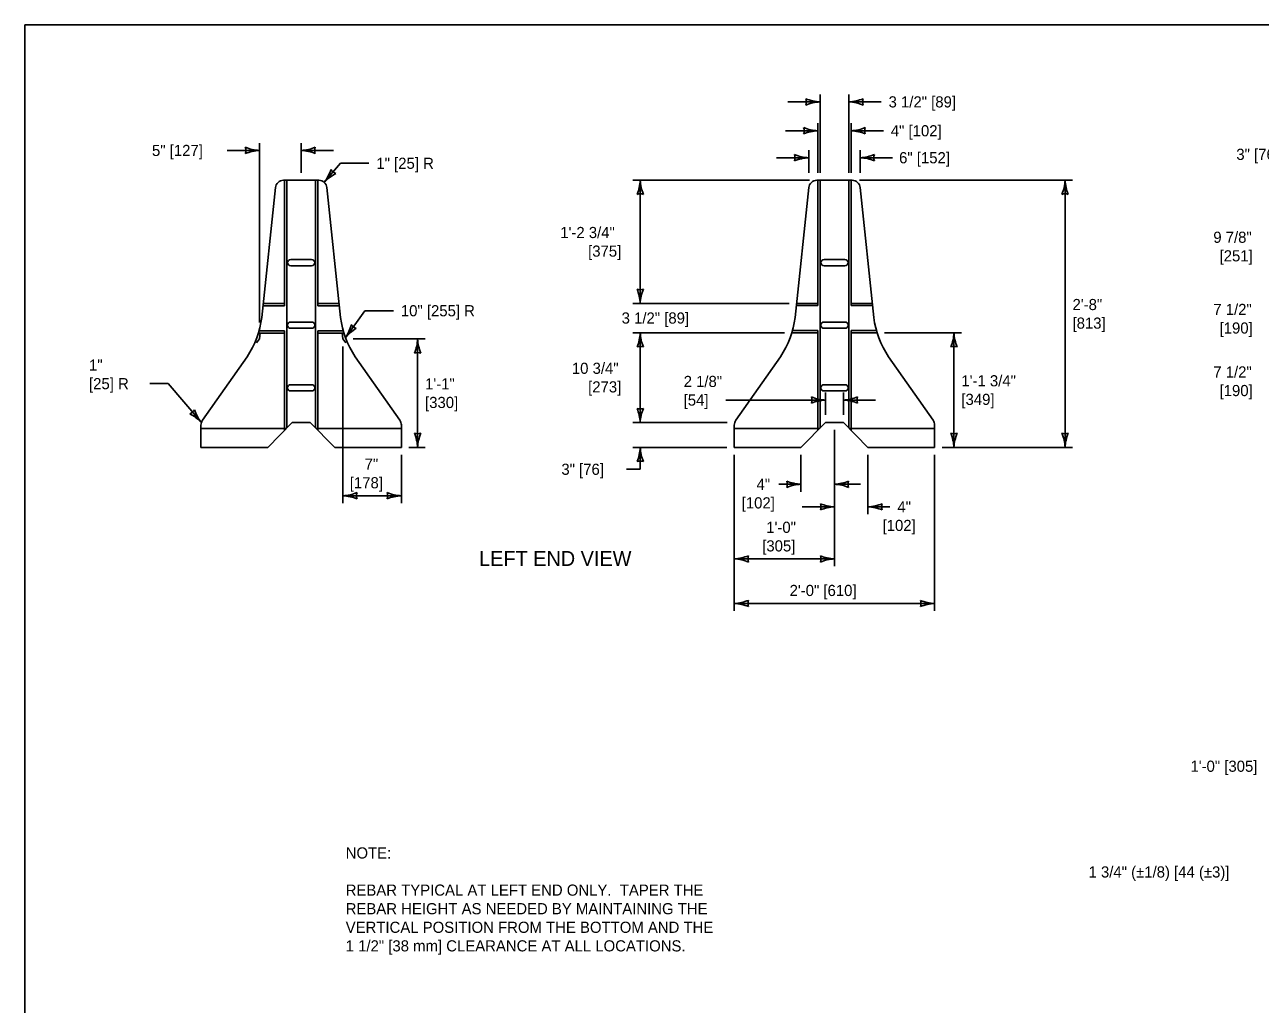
# Model space of a CAD drawing. Extents: x 49991.4 to 50021, y 49987.6 to 50011.4.
# Drawn here: x 49999.38 to 50006.04, y 49993.73 to 49999 of the extents above; entities that cross this region are included whole.
import ezdxf

# ---------------------------------------------------------------- set-up
doc = ezdxf.new("R2010")
doc.units = 0
for name, color, linetype in [('Level 1', 7, 'Continuous'), ('Level 2', 7, 'Continuous'), ('Level 3', 7, 'Continuous'), ('Level 4', 7, 'Continuous')]:
    doc.layers.add(name, color=color, linetype=linetype)

msp = doc.modelspace()

# ---------------------------------------------------------------- linework, layer by layer
at = {"layer": 'Level 1'}
for p, q in [((50000.9678, 49998.1625), (50000.776, 49998.1625)), ((50000.7821, 49998.1625), (50000.7821, 49997.4862)), ((50000.7945, 49998.1625), (50000.7944, 49996.8293)), ((50000.9495, 49998.1625), (50000.9494, 49996.8294)), ((50000.9618, 49998.1625), (50000.9618, 49997.4862)), ((50003.8378, 49998.1624), (50003.6484, 49998.1624)), ((50003.6533, 49998.1624), (50003.6533, 49997.4888)), ((50003.6653, 49998.1624), (50003.6653, 49996.8289)), ((50003.821, 49998.1624), (50003.821, 49996.8288)), ((50003.8329, 49998.1624), (50003.8329, 49997.4888)), ((50000.6596, 49997.4243), (50000.7333, 49998.123)), ((50001.0843, 49997.4242), (50001.0105, 49998.123)), ((50003.5308, 49997.4242), (50003.6046, 49998.1228)), ((50003.9555, 49997.4242), (50003.8817, 49998.1228)), ((50000.8158, 49997.7355), (50000.9281, 49997.7355)), ((50000.8158, 49997.7018), (50000.9281, 49997.7018)), ((50003.6869, 49997.7354), (50003.7993, 49997.7354)), ((50003.6869, 49997.7017), (50003.7993, 49997.7017)), ((50000.7821, 49997.4862), (50000.6661, 49997.4862)), ((50000.7821, 49997.4982), (50000.6674, 49997.4982)), ((50001.0765, 49997.4982), (50000.9618, 49997.4982)), ((50000.9618, 49997.4862), (50001.0777, 49997.4862)), ((50003.6533, 49997.4888), (50003.5376, 49997.4888)), ((50003.6533, 49997.4999), (50003.5388, 49997.4999)), ((50003.9475, 49997.4999), (50003.8329, 49997.4999)), ((50003.8329, 49997.4888), (50003.9487, 49997.4888)), ((50000.6459, 49997.3519), (50000.7821, 49997.3519)), ((50000.7821, 49997.3519), (50000.7821, 49996.8167)), ((50000.9281, 49997.3995), (50000.8158, 49997.3995)), ((50000.8158, 49997.3658), (50000.9281, 49997.3658)), ((50001.098, 49997.3519), (50000.9618, 49997.3519)), ((50000.9618, 49997.3519), (50000.9618, 49996.8168)), ((50003.5178, 49997.3543), (50003.6533, 49997.3543)), ((50003.6533, 49997.3543), (50003.6533, 49996.8167)), ((50003.7993, 49997.3994), (50003.6869, 49997.3994)), ((50003.6869, 49997.3657), (50003.7993, 49997.3657)), ((50003.8329, 49997.3543), (50003.8329, 49996.8167)), ((50003.9685, 49997.3543), (50003.8329, 49997.3543)), ((50000.7821, 49997.3399), (50000.6424, 49997.3399)), ((50001.1014, 49997.3399), (50000.9618, 49997.3399)), ((50003.6533, 49997.3417), (50003.5142, 49997.3417)), ((50003.9721, 49997.3417), (50003.8329, 49997.3417)), ((50000.3405, 49996.8706), (50000.5804, 49997.2129)), ((50001.4033, 49996.8706), (50001.1634, 49997.2129)), ((50003.2118, 49996.8705), (50003.4517, 49997.2128)), ((50004.2745, 49996.8705), (50004.0347, 49997.2128)), ((50000.9281, 49997.0621), (50000.8158, 49997.0621)), ((50000.8158, 49997.0284), (50000.9281, 49997.0284)), ((50003.7993, 49997.062), (50003.6869, 49997.062)), ((50003.6869, 49997.0283), (50003.7993, 49997.0283)), ((50000.3326, 49996.7248), (50000.3325, 49996.8452)), ((50000.6916, 49996.7248), (50000.8239, 49996.8592)), ((50000.9201, 49996.8592), (50000.8239, 49996.8592)), ((50001.0523, 49996.7248), (50000.9201, 49996.8592)), ((50001.4114, 49996.7248), (50001.4113, 49996.8453)), ((50003.2037, 49996.7247), (50003.2038, 49996.8451)), ((50003.5627, 49996.7247), (50003.695, 49996.8591)), ((50003.695, 49996.8591), (50003.7912, 49996.8591)), ((50003.9235, 49996.7247), (50003.7912, 49996.8591)), ((50004.2825, 49996.7247), (50004.2825, 49996.8451)), ((50000.3326, 49996.7248), (50000.6916, 49996.7248)), ((50001.4114, 49996.7248), (50001.0523, 49996.7248)), ((50003.2037, 49996.7247), (50003.5627, 49996.7247)), ((50004.2825, 49996.7247), (50003.9235, 49996.7247))]:
    msp.add_line(p, q, dxfattribs=at)
msp.add_lwpolyline([(49999.3835, 49998.9992), (50016.7501, 49998.9992), (50016.7501, 49987.7988), (49999.3835, 49987.7988)], close=True, dxfattribs=at)
for centre, radius, start, end in [((50000.7773, 49998.1183), 0.0442, 91.675, 173.90567), ((50000.9665, 49998.1183), 0.0442, 6.02753, 88.325), ((50003.6485, 49998.1182), 0.0442, 90.18102, 173.97247), ((50003.8378, 49998.1182), 0.0442, 6.02753, 89.95602), ((50000.8158, 49997.7186), 0.0168, 90, 270), ((50000.9281, 49997.7186), 0.0168, 270, 89.99999), ((50003.6869, 49997.7185), 0.0168, 90, 270), ((50003.7993, 49997.7185), 0.0168, 270, 89.99999), ((50000.2111, 49997.4717), 0.4509, 324.97771, 353.97247), ((50001.5327, 49997.4717), 0.4509, 186.04429, 215.02228), ((50003.0824, 49997.4716), 0.451, 324.97771, 353.97053), ((50004.404, 49997.4716), 0.451, 186.02753, 215.02228), ((50000.8158, 49997.3826), 0.0168, 90, 270), ((50000.9281, 49997.3826), 0.0168, 270, 89.99999), ((50003.6869, 49997.3825), 0.0168, 90, 270), ((50003.7993, 49997.3825), 0.0168, 270, 89.99999), ((50000.8158, 49997.0453), 0.0168, 90, 270), ((50000.9281, 49997.0453), 0.0168, 270, 89.99999), ((50003.6869, 49997.0451), 0.0168, 90, 270), ((50003.7993, 49997.0451), 0.0168, 270, 90), ((50000.3767, 49996.8452), 0.0442, 144.97771, 180), ((50001.3671, 49996.8453), 0.0442, 0, 35.02229), ((50003.248, 49996.8451), 0.0442, 144.97771, 180), ((50004.2383, 49996.8451), 0.0442, 0, 35.02229)]:
    msp.add_arc(centre, radius, start, end, dxfattribs=at)
at = {"layer": 'Level 3'}
for p, q in [((50003.6653, 49998.2024), (50003.6653, 49998.624)), ((50003.821, 49998.2024), (50003.821, 49998.624)), ((50003.6653, 49998.584), (50003.4919, 49998.584)), ((50003.821, 49998.584), (50003.9944, 49998.584)), ((50003.6533, 49998.4286), (50003.4799, 49998.4286)), ((50003.6533, 49998.2024), (50003.6533, 49998.4686)), ((50003.8329, 49998.2024), (50003.8329, 49998.4686)), ((50003.8329, 49998.4286), (50004.0063, 49998.4286)), ((50000.6473, 49997.3971), (50000.6473, 49998.3627)), ((50000.872, 49998.2025), (50000.872, 49998.3627)), ((50000.6473, 49998.3227), (50000.4738, 49998.3227)), ((50001.0454, 49998.3227), (50000.872, 49998.3227)), ((50003.6046, 49998.2835), (50003.4311, 49998.2835)), ((50003.6046, 49998.2024), (50003.6046, 49998.3235)), ((50003.8817, 49998.2024), (50003.8817, 49998.3235)), ((50003.8817, 49998.2835), (50004.0552, 49998.2835)), ((50000.9961, 49998.1512), (50001.083, 49998.2535)), ((50001.083, 49998.2535), (50001.2368, 49998.2535)), ((50003.6084, 49998.1624), (50002.6573, 49998.1624)), ((50002.6973, 49997.4999), (50002.6973, 49998.1624)), ((50003.8778, 49998.1624), (50005.0247, 49998.1624)), ((50004.9847, 49998.1624), (50004.9847, 49996.7247)), ((50003.4988, 49997.4999), (50002.6573, 49997.4999)), ((50001.1104, 49997.3135), (50001.2154, 49997.4602)), ((50001.2154, 49997.4602), (50001.3687, 49997.4602)), ((50000.6473, 49997.3084), (50000.632, 49997.2865)), ((50000.6508, 49997.3413), (50000.6473, 49997.3084)), ((50001.0931, 49997.3413), (50001.0965, 49997.3084)), ((50001.0965, 49997.3084), (50001.1119, 49997.2865)), ((50001.1524, 49997.3084), (50001.539, 49997.3084)), ((50001.499, 49996.7248), (50001.499, 49997.3084)), ((50003.4742, 49997.3417), (50002.6573, 49997.3417)), ((50002.6973, 49997.3417), (50002.6973, 49996.8584)), ((50004.0121, 49997.3417), (50004.4264, 49997.3417)), ((50004.3864, 49996.7247), (50004.3864, 49997.3417)), ((50001.0965, 49997.2684), (50001.0965, 49996.4245)), ((50000.1561, 49997.0678), (50000.0563, 49997.0678)), ((50000.3346, 49996.8585), (50000.1561, 49997.0678)), ((50003.695, 49996.8991), (50003.695, 49997.0196)), ((50003.7912, 49996.8991), (50003.7912, 49997.0196)), ((50003.695, 49996.9796), (50003.1577, 49996.9796)), ((50003.7912, 49996.9796), (50003.9646, 49996.9796)), ((50003.1658, 49996.8584), (50002.6573, 49996.8584)), ((50003.7431, 49996.8191), (50003.7431, 49996.0848)), ((50001.4114, 49996.6848), (50001.4114, 49996.4245)), ((50001.4514, 49996.7248), (50001.539, 49996.7248)), ((50003.1637, 49996.7247), (50002.6573, 49996.7247)), ((50002.6973, 49996.7247), (50002.6973, 49996.607)), ((50003.2037, 49996.6847), (50003.2037, 49995.8449)), ((50003.5627, 49996.6847), (50003.5627, 49996.4863)), ((50003.9235, 49996.6847), (50003.9235, 49996.3648)), ((50004.2825, 49996.6847), (50004.2825, 49995.8449)), ((50004.3225, 49996.7247), (50005.0247, 49996.7247)), ((50002.6973, 49996.607), (50002.6239, 49996.607)), ((50003.5627, 49996.5263), (50003.4443, 49996.5263)), ((50003.7431, 49996.5263), (50003.8835, 49996.5263)), ((50001.0965, 49996.4645), (50001.4114, 49996.4645)), ((50003.5697, 49996.4048), (50003.7431, 49996.4048)), ((50004.0419, 49996.4048), (50003.9235, 49996.4048)), ((50003.2056, 49996.1248), (50003.7431, 49996.1248)), ((50003.2037, 49995.8849), (50004.2825, 49995.8849))]:
    msp.add_line(p, q, dxfattribs=at)
for centre, radius, start, end in [((50003.6745, 49998.8062), 0.2223, 247.45601, 267.63952), ((50003.5371, 49998.584), 0.0548, 342.13882, 17.86118), ((50003.6768, 49998.3513), 0.233, 92.82731, 112.07716), ((50003.8095, 49998.8167), 0.233, 272.82731, 292.07716), ((50003.8119, 49998.3619), 0.2223, 67.45601, 87.63952), ((50003.9492, 49998.584), 0.0548, 162.13882, 197.86118), ((50003.6625, 49998.6508), 0.2223, 247.45601, 267.63952), ((50003.5251, 49998.4286), 0.0548, 342.13882, 17.86118), ((50003.6648, 49998.1959), 0.233, 92.82731, 112.07716), ((50003.8214, 49998.6614), 0.233, 272.82731, 292.07716), ((50003.8238, 49998.2065), 0.2223, 67.45601, 87.63952), ((50003.9611, 49998.4286), 0.0548, 162.13882, 197.86118), ((50000.6564, 49998.5448), 0.2223, 247.45601, 267.63952), ((50000.519, 49998.3227), 0.0548, 342.13882, 17.86118), ((50000.6587, 49998.0899), 0.233, 92.82731, 112.07716), ((50000.8605, 49998.5554), 0.233, 272.82731, 292.07716), ((50000.8628, 49998.1005), 0.2223, 67.45601, 87.63952), ((50001.0002, 49998.3227), 0.0548, 162.13882, 197.86118), ((50003.6137, 49998.5056), 0.2223, 247.45601, 267.63952), ((50003.4764, 49998.2835), 0.0548, 342.13882, 17.86118), ((50003.6161, 49998.0508), 0.233, 92.82731, 112.07716), ((50003.8702, 49998.5162), 0.233, 272.82731, 292.07716), ((50003.8726, 49998.0614), 0.2223, 67.45601, 87.63952), ((50004.01, 49998.2835), 0.0548, 162.13882, 197.86118), ((50000.8113, 49998.293), 0.233, 322.49168, 341.74153), ((50001.0791, 49998.2489), 0.0548, 211.80319, 247.52555), ((50001.1595, 49998.0004), 0.2223, 117.12038, 137.30389), ((50002.4752, 49998.1716), 0.2223, 337.45601, 357.63952), ((50002.93, 49998.1739), 0.233, 182.82731, 202.07716), ((50004.7625, 49998.1716), 0.2223, 337.45601, 357.63952), ((50005.2174, 49998.1739), 0.233, 182.82731, 202.07716), ((50002.6973, 49998.0342), 0.0548, 72.13882, 107.86118), ((50004.9847, 49998.0342), 0.0548, 72.13882, 107.86118), ((50002.6973, 49997.6281), 0.0548, 252.13882, 287.86118), ((50002.4646, 49997.4884), 0.233, 2.82731, 22.07716), ((50002.9194, 49997.4907), 0.2223, 157.45601, 177.63952), ((50000.9145, 49997.4396), 0.233, 327.22542, 346.47527), ((50001.2857, 49997.1768), 0.2223, 121.85412, 142.03763), ((50001.185, 49997.4178), 0.0548, 216.53693, 252.25929), ((50001.2768, 49997.3176), 0.2223, 337.45601, 357.63952), ((50001.7317, 49997.3199), 0.233, 182.82731, 202.07716), ((50002.4752, 49997.3509), 0.2223, 337.45601, 357.63952), ((50002.93, 49997.3532), 0.233, 182.82731, 202.07716), ((50004.1643, 49997.3509), 0.2223, 337.45601, 357.63952), ((50004.6191, 49997.3532), 0.233, 182.82731, 202.07716), ((50001.499, 49997.1802), 0.0548, 72.13882, 107.86118), ((50002.6973, 49997.2135), 0.0548, 72.13882, 107.86118), ((50004.3864, 49997.2135), 0.0548, 72.13882, 107.86118), ((50003.7042, 49997.2017), 0.2223, 247.45601, 267.63952), ((50003.5668, 49996.9796), 0.0548, 342.13882, 17.86118), ((50003.7065, 49996.7468), 0.233, 92.82731, 112.07716), ((50003.7797, 49997.2123), 0.233, 272.82731, 292.07716), ((50003.7821, 49996.7574), 0.2223, 67.45601, 87.63952), ((50003.9194, 49996.9796), 0.0548, 162.13882, 197.86118), ((50000.2514, 49996.9561), 0.0548, 292.59303, 328.31539), ((50000.165, 49996.6988), 0.233, 43.28152, 62.53137), ((50000.5096, 49996.9957), 0.2223, 197.91022, 218.09373), ((50002.6973, 49996.9866), 0.0548, 252.13882, 287.86118), ((50002.4646, 49996.8469), 0.233, 2.82731, 22.07716), ((50002.9194, 49996.8493), 0.2223, 157.45601, 177.63952), ((50001.499, 49996.853), 0.0548, 252.13882, 287.86118), ((50001.2662, 49996.7133), 0.233, 2.82731, 22.07716), ((50001.7211, 49996.7156), 0.2223, 157.45601, 177.63952), ((50004.3864, 49996.8529), 0.0548, 252.13882, 287.86118), ((50004.1537, 49996.7132), 0.233, 2.82731, 22.07716), ((50004.6086, 49996.7155), 0.2223, 157.45601, 177.63952), ((50004.9847, 49996.8529), 0.0548, 252.13882, 287.86118), ((50004.7519, 49996.7132), 0.233, 2.82731, 22.07716), ((50005.2068, 49996.7155), 0.2223, 157.45601, 177.63952), ((50002.4752, 49996.7339), 0.2223, 337.45601, 357.63952), ((50002.93, 49996.7362), 0.233, 182.82731, 202.07716), ((50002.6973, 49996.5965), 0.0548, 72.13882, 107.86118), ((50001.085, 49996.6973), 0.233, 272.82731, 292.07716), ((50001.2247, 49996.4645), 0.0548, 162.13882, 197.86118), ((50001.4205, 49996.6867), 0.2223, 247.45601, 267.63952), ((50001.2831, 49996.4645), 0.0548, 342.13882, 17.86118), ((50003.5719, 49996.7485), 0.2223, 247.45601, 267.63952), ((50003.4345, 49996.5263), 0.0548, 342.13882, 17.86118), ((50003.5742, 49996.2936), 0.233, 92.82731, 112.07716), ((50003.7316, 49996.7591), 0.233, 272.82731, 292.07716), ((50003.734, 49996.3042), 0.2223, 67.45601, 87.63952), ((50003.8713, 49996.5263), 0.0548, 162.13882, 197.86118), ((50001.0873, 49996.2424), 0.2223, 67.45601, 87.63952), ((50001.4228, 49996.2318), 0.233, 92.82731, 112.07716), ((50003.7523, 49996.6269), 0.2223, 247.45601, 267.63952), ((50003.6149, 49996.4048), 0.0548, 342.13882, 17.86118), ((50003.912, 49996.6375), 0.233, 272.82731, 292.07716), ((50004.0517, 49996.4048), 0.0548, 162.13882, 197.86118), ((50003.7546, 49996.1721), 0.233, 92.82731, 112.07716), ((50003.9144, 49996.1827), 0.2223, 67.45601, 87.63952), ((50003.1922, 49996.3575), 0.233, 272.82731, 292.07716), ((50003.1946, 49995.9027), 0.2223, 67.45601, 87.63952), ((50003.332, 49996.1248), 0.0548, 162.13882, 197.86118), ((50003.7523, 49996.3469), 0.2223, 247.45601, 267.63952), ((50003.6149, 49996.1248), 0.0548, 342.13882, 17.86118), ((50003.7546, 49995.8921), 0.233, 92.82731, 112.07716), ((50003.1922, 49996.1176), 0.233, 272.82731, 292.07716), ((50003.1946, 49995.6628), 0.2223, 67.45601, 87.63952), ((50003.332, 49995.8849), 0.0548, 162.13882, 197.86118), ((50004.2917, 49996.107), 0.2223, 247.45601, 267.63952), ((50004.1543, 49995.8849), 0.0548, 342.13882, 17.86118), ((50004.294, 49995.6522), 0.233, 92.82731, 112.07716)]:
    msp.add_arc(centre, radius, start, end, dxfattribs=at)
at = {"layer": 'Level 4'}
for p, q in [((50000.7917, 49996.8265), (50000.3325, 49996.8265)), ((50001.4113, 49996.8265), (50000.9522, 49996.8265)), ((50003.6628, 49996.8264), (50003.2038, 49996.8264)), ((50004.2825, 49996.8264), (50003.8234, 49996.8264))]:
    msp.add_line(p, q, dxfattribs=at)

# ---------------------------------------------------------------- texts
at = {"layer": 'Level 2'}
for s, height, p in [('3 1/2" [89]', 0.06, (50004.0344, 49998.554)), ('4" [102]', 0.06, (50004.0463, 49998.3986)), ('5" [127]', 0.06, (50000.0688, 49998.2927)), ('1" [25] R', 0.06, (50001.2768, 49998.2235)), ('6" [152]', 0.06, (50004.091, 49998.2535)), ('3" [76]', 0.06, (50005.9066, 49998.2717)), ('1\'-2 3/4"', 0.06, (50002.2669, 49997.8511)), ('9 7/8"', 0.06, (50005.7827, 49997.8256)), ('[375]', 0.06, (50002.4169, 49997.7511)), ('[251]', 0.06, (50005.8164, 49997.7256)), ('10" [255] R', 0.06, (50001.4087, 49997.4302)), ('2\'-8"', 0.06, (50005.0247, 49997.4635)), ('7 1/2"', 0.06, (50005.7827, 49997.4372)), ('3 1/2" [89]', 0.06, (50002.5973, 49997.391)), ('[813]', 0.06, (50005.0247, 49997.3635)), ('[190]', 0.06, (50005.8164, 49997.3372)), ('1" ', 0.06, (49999.7297, 49997.1378)), ('10 3/4"', 0.06, (50002.3293, 49997.1204)), ('7 1/2"', 0.06, (50005.7827, 49997.1007)), ('[25] R', 0.06, (49999.7297, 49997.0378)), ('1\'-1"', 0.06, (50001.539, 49997.0366)), ('[273]', 0.06, (50002.4169, 49997.0204)), ('2 1/8"', 0.06, (50002.9312, 49997.0496)), ('1\'-1 3/4"', 0.06, (50004.4264, 49997.0532)), ('[54]', 0.06, (50002.9312, 49996.9496)), ('[349]', 0.06, (50004.4264, 49996.9532)), ('[190]', 0.06, (50005.8164, 49997.0007)), ('[330]', 0.06, (50001.539, 49996.9366)), ('7"', 0.06, (50001.2136, 49996.6045)), ('3" [76]', 0.06, (50002.2728, 49996.577)), ('[178]', 0.06, (50001.1337, 49996.5045)), ('4"', 0.06, (50003.3236, 49996.4963)), ('[102]', 0.06, (50003.2437, 49996.3963)), ('4"', 0.06, (50004.0819, 49996.3748)), ('1\'-0"', 0.06, (50003.3759, 49996.2648)), ('[102]', 0.06, (50004.0021, 49996.2748)), ('[305]', 0.06, (50003.3541, 49996.1648)), ('LEFT END VIEW', 0.08, (50001.8298, 49996.087)), ('2\'-0" [610]', 0.06, (50003.5016, 49995.9249)), ('1\'-0" [305]', 0.06, (50005.6597, 49994.9791)), ('NOTE:', 0.06, (50001.1116, 49994.5124)), ('1 3/4" (±1/8) [44 (±3)]', 0.06, (50005.111, 49994.4101)), ('REBAR TYPICAL AT LEFT END ONLY.  TAPER THE', 0.06, (50001.1116, 49994.3124)), ('REBAR HEIGHT AS NEEDED BY MAINTAINING THE', 0.06, (50001.1116, 49994.2124)), ('VERTICAL POSITION FROM THE BOTTOM AND THE', 0.06, (50001.1116, 49994.1124)), ('1 1/2" [38 mm] CLEARANCE AT ALL LOCATIONS.', 0.06, (50001.1116, 49994.0124))]:
    msp.add_text(s, height=height, dxfattribs=at).set_placement(p)

doc.saveas('drawing.dxf')
